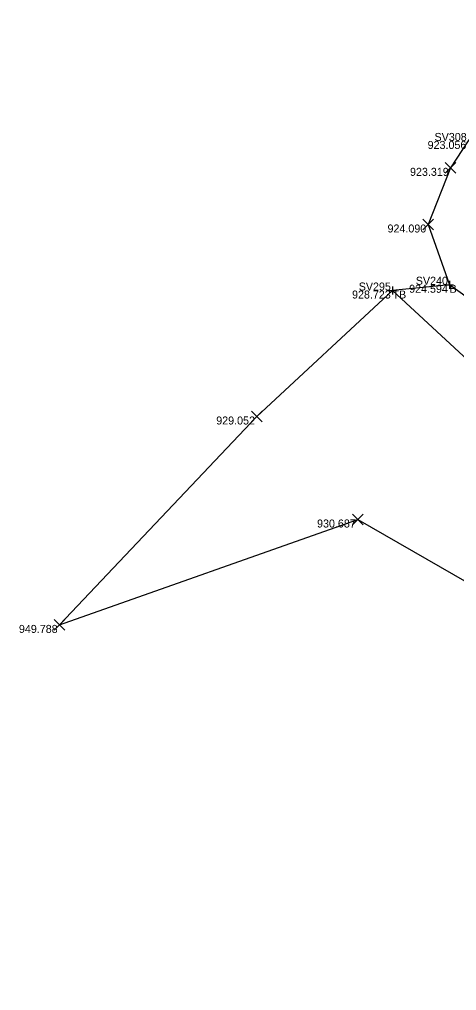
# Model space of a CAD drawing. Extents: x 1988835 to 1989144, y 657973 to 659339.
# Drawn here: x 1988835 to 1988889.6, y 658616.1 to 658737.4 of the extents above; entities that cross this region are included whole.
import ezdxf

# ---------------------------------------------------------------- set-up
doc = ezdxf.new("R2010")
doc.units = 0
for name, color, linetype in [('DT_X_Terrain_Boundary', 7, 'Continuous'), ('SV_X_Break_Lines', 7, 'Continuous'), ('SV_X_Random_Point', 7, 'Continuous'), ('SV_X_Shot_Marker', 7, 'Continuous'), ('SV_X_Text_Comment', 7, 'Continuous'), ('SV_X_Top_of_Bank', 7, 'Continuous'), ('UT_X_Telecom', 7, 'Continuous'), ('UT_X_Telecom_Cells', 7, 'Continuous')]:
    doc.layers.add(name, color=color, linetype=linetype)

msp = doc.modelspace()

# ---------------------------------------------------------------- linework, layer by layer
at = {"layer": 'DT_X_Terrain_Boundary'}
msp.add_lwpolyline([(1988987.83, 658845.23), (1988984.81, 658799.59), (1988977.84, 658799.78), (1988968.83, 658798.91), (1988942.79, 658792.82), (1988927.35, 658779.11), (1988913.54, 658771.15), (1988908.13, 658758.46), (1988901.04, 658731.18), (1988897.02, 658728.69), (1988894.52, 658726.61), (1988891.03, 658722.22), (1988888.81, 658718.86), (1988886.03, 658711.78), (1988888.7, 658704.25), (1988881.58, 658703.53), (1988864.62, 658687.79), (1988839.99, 658661.75), (1988877.26, 658674.92), (1988925.04, 658647.45), (1988929, 658641.52), (1988939.92, 658638.36), (1988953.75, 658630), (1988967.24, 658593.53)], dxfattribs=at)
at = {"layer": 'SV_X_Break_Lines'}
msp.add_lwpolyline([(1988950.44, 658683.54), (1988950.97, 658681.82), (1988947.27, 658678.12), (1988941.78, 658670.76), (1988909.76, 658689.09), (1988888.7, 658704.25)], dxfattribs=at)
at = {"layer": 'SV_X_Random_Point'}
for p, q in [((1988888.14, 658718.2), (1988889.47, 658719.53)), ((1988888.14, 658719.53), (1988889.47, 658718.2)), ((1988885.36, 658711.12), (1988886.69, 658712.45)), ((1988885.36, 658712.45), (1988886.69, 658711.12)), ((1988863.96, 658687.12), (1988865.29, 658688.46)), ((1988863.96, 658688.46), (1988865.29, 658687.12)), ((1988876.6, 658674.25), (1988877.93, 658675.59)), ((1988876.6, 658675.59), (1988877.93, 658674.25)), ((1988839.32, 658661.08), (1988840.66, 658662.42)), ((1988839.32, 658662.42), (1988840.66, 658661.08))]:
    msp.add_line(p, q, dxfattribs=at)
at = {"layer": 'SV_X_Shot_Marker'}
for p, q in [((1988888.7, 658704.75), (1988888.7, 658703.75)), ((1988881.58, 658704.03), (1988881.58, 658703.03)), ((1988888.2, 658704.25), (1988889.2, 658704.25)), ((1988888.7, 658704.25), (1988888.7, 658704.25)), ((1988881.08, 658703.53), (1988882.08, 658703.53)), ((1988881.58, 658703.53), (1988881.58, 658703.53))]:
    msp.add_line(p, q, dxfattribs=at)
at = {"layer": 'SV_X_Top_of_Bank'}
msp.add_lwpolyline([(1988925.04, 658647.45), (1988930.24, 658657.35), (1988925.34, 658673.89), (1988916.87, 658675.49), (1988894.86, 658691.24), (1988881.58, 658703.53)], dxfattribs=at)

# ---------------------------------------------------------------- texts
at = {"layer": 'SV_X_Text_Comment'}
for s, p in [('SV308', (1988886.83, 658722.22)), ('SV240', (1988884.49, 658704.25)), ('SV295', (1988877.36, 658703.53))]:
    msp.add_text(s, height=1, dxfattribs=at).set_placement(p)
at = {"layer": 'UT_X_Telecom'}
for s, p in [('B', (1988888.7, 658703.25)), ('TB', (1988881.58, 658702.53))]:
    msp.add_text(s, height=1, dxfattribs=at).set_placement(p)
at = {"layer": 'UT_X_Telecom_Cells'}
for s, p in [('923.056', (1988885.97, 658721.22)), ('923.319', (1988883.77, 658717.86)), ('924.090', (1988880.96, 658710.78)), ('928.723', (1988876.53, 658702.53)), ('924.594', (1988883.66, 658703.25)), ('929.052', (1988859.57, 658686.79)), ('930.687', (1988872.16, 658673.92)), ('949.788', (1988834.93, 658660.75))]:
    msp.add_text(s, height=1, dxfattribs=at).set_placement(p)

doc.saveas('drawing.dxf')
